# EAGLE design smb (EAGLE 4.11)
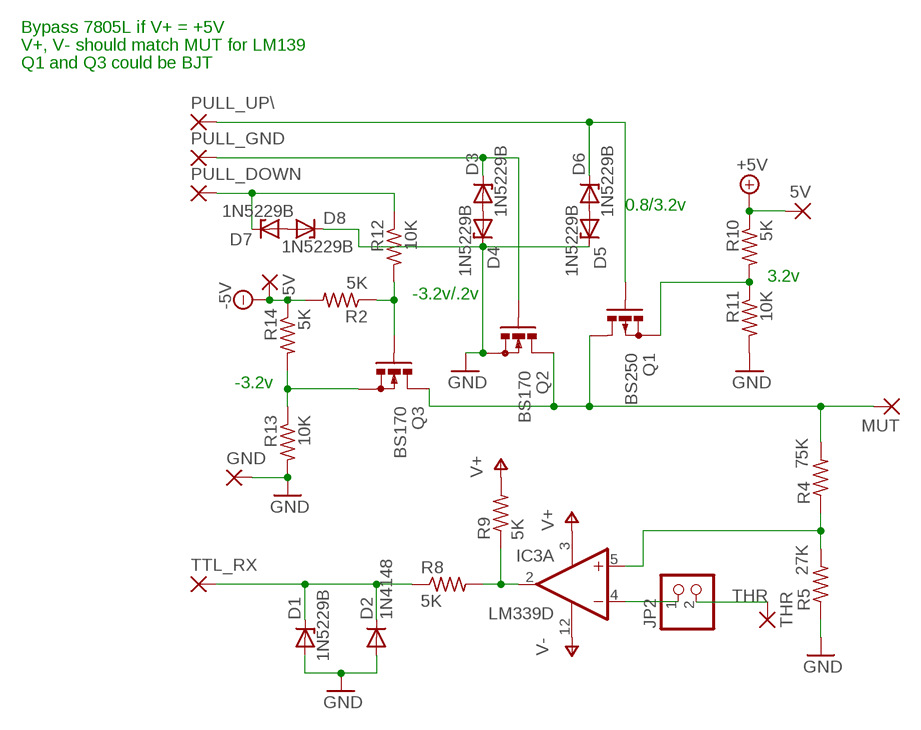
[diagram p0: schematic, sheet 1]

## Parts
5V  1,6/0,9  [1,6/0,9]
-5V  1,6/0,9  [1,6/0,9]
D1  1N5229B  ZENER-DIODESOD80C  [SOD80C]
D2  1N4148  DIODE-SOD80C  [SOD80C]
D3  1N5229B  ZENER-DIODESOD80C  [SOD80C]
D4  1N5229B  ZENER-DIODESOD80C  [SOD80C]
D5  1N5229B  ZENER-DIODESOD80C  [SOD80C]
D6  1N5229B  ZENER-DIODESOD80C  [SOD80C]
D7  1N5229B  ZENER-DIODESOD80C  [SOD80C]
D8  1N5229B  ZENER-DIODESOD80C  [SOD80C]
GND  1,6/0,9  [1,6/0,9]
IC3  LM339D  [SO14]
JP2  PINHD-1X2  [1X02]
MUT  1,6/0,9  [1,6/0,9]
PULL_DOWN  1,6/0,9  [1,6/0,9]
PULL_GND  1,6/0,9  [1,6/0,9]
PULL_UP\  1,6/0,9  [1,6/0,9]
Q1  BS250  [SOT54E]
Q2  BS170  [SOT54E]
Q3  BS170  [SOT54E]
R2  5K  R-US_M1206  [M1206]
R4  75K  R-US_M1206  [M1206]
R5  27K  R-US_M1206  [M1206]
R8  5K  R-US_M1206  [M1206]
R9  5K  R-US_M1206  [M1206]
R10  5K  R-US_M1206  [M1206]
R11  10K  R-US_M1206  [M1206]
R12  10K  R-US_M1206  [M1206]
R13  10K  R-US_M1206  [M1206]
R14  5K  R-US_M1206  [M1206]
THR  1,6/0,9  [1,6/0,9]
TTL_RX  1,6/0,9  [1,6/0,9]

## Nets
+5V: 5V.1(P) R10.1
-5V: -5V.1(P) R2.2 R14.1
GND: D1.A D2.A D4.C D5.C D8.C GND.1(P) Q2.S R5.1 R11.2 R13.2
N$1: MUT.1(P) Q1.D Q2.D Q3.D R4.2
N$2: Q3.G R2.1 R12.2
N$3: D3.C PULL_GND.1(P) Q2.G
N$4: D7.C PULL_DOWN.1(P) R12.1
N$5: Q1.S R10.2 R11.1
N$6: D5.A D6.A
N$7: IC3.5(A:+IN) R4.1 R5.2
N$8: IC3.4(A:-IN) JP2.1
N$9: IC3.2(A:OUT) R8.2 R9.1
N$10: D6.C PULL_UP\.1(P) Q1.G
N$11: D3.A D4.A
N$12: D1.C D2.C R8.1 TTL_RX.1(P)
N$15: D7.A D8.A
N$16: Q3.S R13.1 R14.2
THR: JP2.2 THR.1(P)
V+: IC3.3(P:V+) R9.2
V-: IC3.12(P:GND)
Unconnected: IC3.1(B:OUT) IC3.6(B:-IN) IC3.7(B:+IN) IC3.8(C:-IN) IC3.9(C:+IN) IC3.10(D:-IN) IC3.11(D:+IN) IC3.13(D:OUT) IC3.14(C:OUT)

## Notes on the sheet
- Bypass 7805L if V+ = +5V
- V+, V- should match MUT for LM139
- Q1 and Q3 could be BJT
- 0.8/3.2v
- 3.2v
- -3.2v/.2v
- -3.2v

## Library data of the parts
5V -5V GND MUT PULL_DOWN PULL_GND PULL_UP\ THR TTL_RX = wirepad:1,6/0,9: THROUGH-HOLE PAD
D1 D3-D8 = diode:ZENER-DIODE: Z-Diode
D2 = diode:DIODE-: DIODE
IC3 = linear:LM339: Low Power Low Offset Voltage Quad Comparators with open collector; LM139/LM239/LM339/LM2901/LM3302
JP2 = pinhead:PINHD-1X2: PIN HEADER
Q1 = transistor-small-signal:BS250: P-CHANNEL MOS FET
Q2 Q3 = transistor-small-signal:BS170: N-CHANNEL MOS FET
R2 R4 R5 R8-R14 = rcl:R-US_: RESISTOR, American symbol

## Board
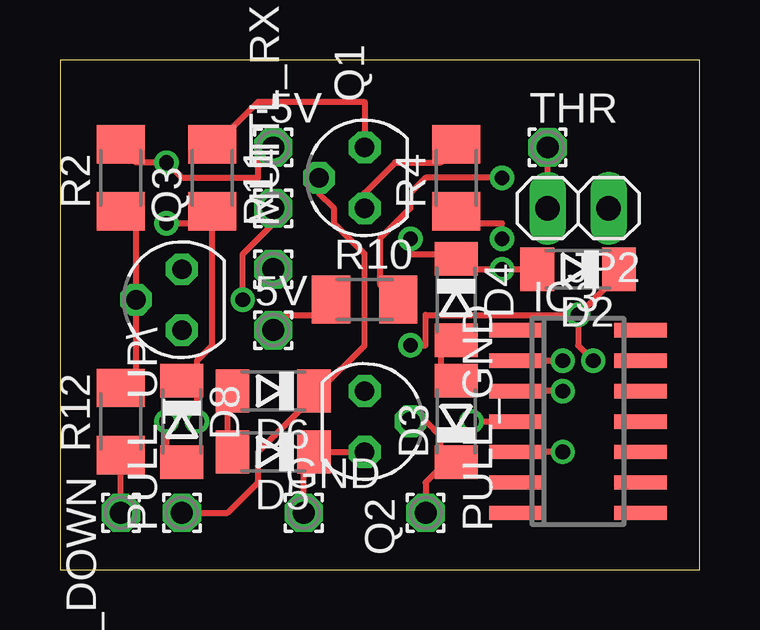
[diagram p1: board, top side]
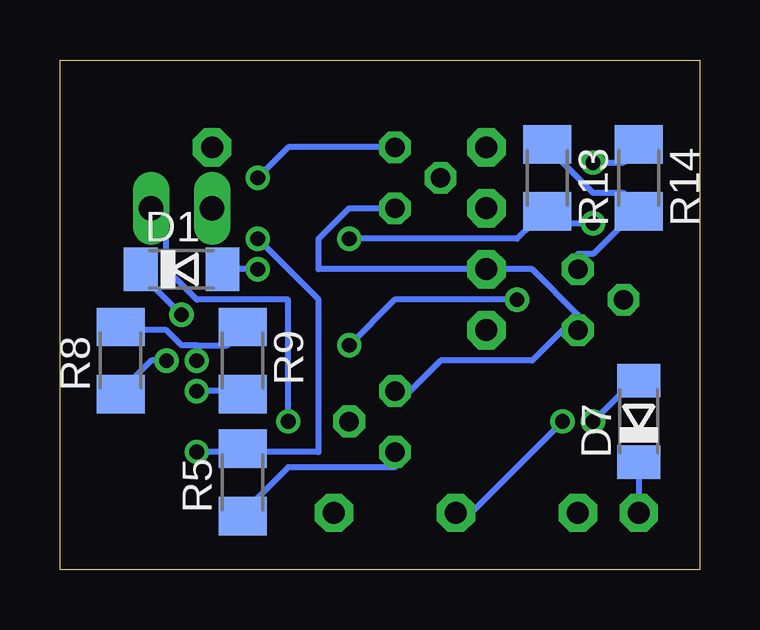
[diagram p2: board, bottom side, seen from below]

Size 26.65 x 21.26 mm. Coordinates in mm from the lower left corner, seen from the top.
Outline: 0,0 26.65,0 26.65,21.26 0,21.26 0,0
Copper layers (1*16): Top 0.035mm / dielectric 1.5mm / Bottom 0.035mm
Design rules "default": minimum track width 10mil, minimum drill 24mil, track to track 8mil, track to pad 8mil, pad to pad 8mil, via to via 8mil, smd to smd 8mil, copper to edge 40mil, drill to drill 8mil, minimum pad ring 10mil, minimum via ring 8mil, stop-mask expansion 4mil, vias tented up to drill 0mil, thermal gap 10mil

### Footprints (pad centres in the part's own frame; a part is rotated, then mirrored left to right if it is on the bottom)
1,6/0,9 = drill 0.914 pad 1.6 octagon: 1 0,0
SOD80C = smd 1.4 x 1.8: A 1.7,0; C -1.7,0
SO14 = smd 0.6 x 2.2: 1 -3.81,-2.6; 2 -2.54,-2.6; 3 -1.27,-2.6; 4 0,-2.6; 5 1.27,-2.6; 6 2.54,-2.6; 7 3.81,-2.6; 8 3.81,2.6; 9 2.54,2.6; 10 1.27,2.6; 11 0,2.6; 12 -1.27,2.6; 13 -2.54,2.6; 14 -3.81,2.6
1X02 = drill 1.016 long: 1 -1.27,0; 2 1.27,0
SOT54E = drill 0.813 octagon: D -1.27,0; G 0,1.905; S 1.27,0
M1206 = smd 1.6 x 2: 1 -1.4,0; 2 1.4,0

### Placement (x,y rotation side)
5V  8.88,10 0 top
-5V  8.88,17.62 0 top
D1  21.59,12.54 0 bottom
D2  21.59,12.54 180 top
D3  16.51,6.18 90 top
D4  16.51,11.27 270 top
D5  8.88,4.92 180 top
D6  8.88,7.46 180 top
D7  2.54,6.18 90 bottom
D8  5.08,6.18 270 top
GND  10.15,2.38 0 top
IC3  21.59,6.18 270 top
JP2  21.59,15.08 180 top
MUT  8.88,12.54 90 top
PULL_DOWN  2.54,2.38 270 top
PULL_GND  15.23,2.38 0 top
PULL_UP\  5.08,2.38 90 top
Q1  12.69,16.35 90 top
Q2  12.69,6.18 270 top
Q3  5.08,11.27 90 top
R2  2.54,16.35 90 top
R4  16.51,16.35 90 top
R5  19.05,3.65 90 bottom
R8  24.12,8.73 90 bottom
R9  19.05,8.73 270 bottom
R10  12.69,11.27 0 top
R11  6.34,16.35 270 top
R12  2.54,6.18 90 top
R13  6.34,16.35 270 bottom
R14  2.54,16.35 270 bottom
THR  20.32,17.62 0 top
TTL_RX  8.88,15.08 90 top

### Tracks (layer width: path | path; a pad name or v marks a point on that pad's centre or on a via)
+5V
  Top 0.254: R10.1 10.79,10.63 8.88,10.63 5V.1
-5V  (via drill 0.61)
  Top 0.254: R14.1 3.17,16.98 v4.44,16.98 5.08,16.35 8.25,16.35 8.25,17.62 -5V.1
  Bottom 0.254: v4.44,16.98 3.17,16.98 R14.1
GND  (via drill 0.61)
  Top 0.254: GND.1 10.15,3.01 10.15,4.28 D5.C 10.79,4.92 12.06,4.92 Q2.S | D2.A 19.68,12.54 v18.41,12.54 17.14,12.54 D4.C 15.87,13.17 14.6,13.17 v14.6,13.81 | v4.44,14.44 5.71,14.44 R11.2 6.34,14.44 6.34,9.36 5.71,8.73 5.71,8.09 D8.C 5.71,7.46 v5.71,6.18
  Bottom 0.254: R5.1 18.41,3.01 17.14,4.28 12.69,4.28 Q2.S | v18.41,12.54 19.68,12.54 D2.A | v4.44,14.44 5.71,14.44 R11.2 6.98,14.44 7.62,13.81 v14.6,13.81 | v5.71,6.18 9.52,2.38 GND.1
N$1
  Top 0.254: R4.2 15.87,16.98 13.96,16.98 12.69,15.71 Q1.D
  Bottom 0.254: Q2.D 12.06,7.46 10.79,8.73 6.98,8.73 5.71,10 Q3.D 5.08,10.63 6.98,12.54 8.25,12.54 MUT.1 9.52,12.54 15.87,12.54 15.87,13.81 14.6,15.08 13.33,15.08 Q1.D
N$2
  Top 0.254: R12.2 3.17,8.09 3.17,10.63 Q3.G 3.17,11.9 3.17,14.44 R2.1
N$3
  Top 0.254: PULL_GND.1 15.23,3.01 15.23,3.65 15.87,4.28 D3.C 15.87,4.92 15.87,5.55 15.23,6.18 Q2.G
N$4
  Top 0.254: R12.1 2.54,4.28 2.54,3.01 PULL_DOWN.1
  Bottom 0.254: D7.C 2.54,4.28 2.54,3.01 PULL_DOWN.1
N$5  (via drill 0.61)
  Top 0.254: v18.41,16.35 15.23,16.35 14.6,15.71 14.6,15.08 13.33,13.81 13.33,11.9 R10.2 | R11.1 6.98,18.25 8.25,19.52 12.69,19.52 12.69,18.25 Q1.S
  Bottom 0.254: v18.41,16.35 17.14,17.62 13.33,17.62 Q1.S
N$6
  Top 0.254: D5.A 6.98,5.55 6.98,6.82 D6.A
N$7  (via drill 0.61)
  Top 0.254: v18.41,13.81 18.41,14.44 17.14,14.44 R4.1 | v20.95,4.92 19.68,4.92 IC3.5
  Bottom 0.254: v18.41,13.81 15.87,11.27 15.87,4.92 18.41,4.92 R5.2 19.68,4.92 v20.95,4.92
N$8  (via drill 0.61)
  Top 0.254: v17.14,6.18 18.41,6.18 IC3.4
  Bottom 0.254: v17.14,6.18 17.14,11.27 20.95,11.27 22.22,12.54 22.22,14.44 JP2.1
N$9  (via drill 0.61)
  Top 0.254: v20.95,8.73 19.68,8.73 IC3.2
  Bottom 0.254: 20.95,9.36 21.59,9.36 22.22,10 23.49,10 R8.2 | 20.95,9.36 19.68,9.36 R9.1 | v20.95,8.73 20.95,9.36
N$10
  Top 0.254: PULL_UP\.1 5.71,2.38 6.98,2.38 8.25,3.65 8.25,4.92 10.15,6.82 D6.C 10.79,7.46 12.69,9.36 12.69,13.17 11.42,14.44 11.42,15.08 10.79,15.71 Q1.G
N$11
  Top 0.254: D3.A 15.87,8.09 15.87,9.36 D4.A
N$12  (via drill 0.61)
  Top 0.254: v21.59,10.63 22.86,11.9 D2.C | v22.22,8.73 21.59,9.36 v21.59,10.63 | v7.62,11.27 7.62,13.17 8.88,14.44 TTL_RX.1 | v14.6,9.36 15.23,9.36 15.23,10.63 v21.59,10.63
  Bottom 0.254: v21.59,10.63 22.86,11.9 D2.C | v22.22,8.73 22.86,8.73 23.49,8.09 R8.1 | v7.62,11.27 12.69,11.27 v14.6,9.36
N$15  (via drill 0.61)
  Top 0.254: v4.44,6.18 4.44,4.92 D8.A
  Bottom 0.254: v4.44,6.18 3.17,7.46 D7.A
N$16
  Bottom 0.254: Q3.S 5.08,13.17 4.44,13.17 3.17,14.44 R14.2 3.17,15.71 4.44,15.71 5.71,16.98 R13.1
THR
  Top 0.254: JP2.2 20.32,16.35 20.32,16.98 THR.1
V+  (via drill 0.61)
  Top 0.254: v20.95,7.46 19.68,7.46 IC3.3
  Bottom 0.254: v20.95,7.46 19.68,7.46 R9.2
